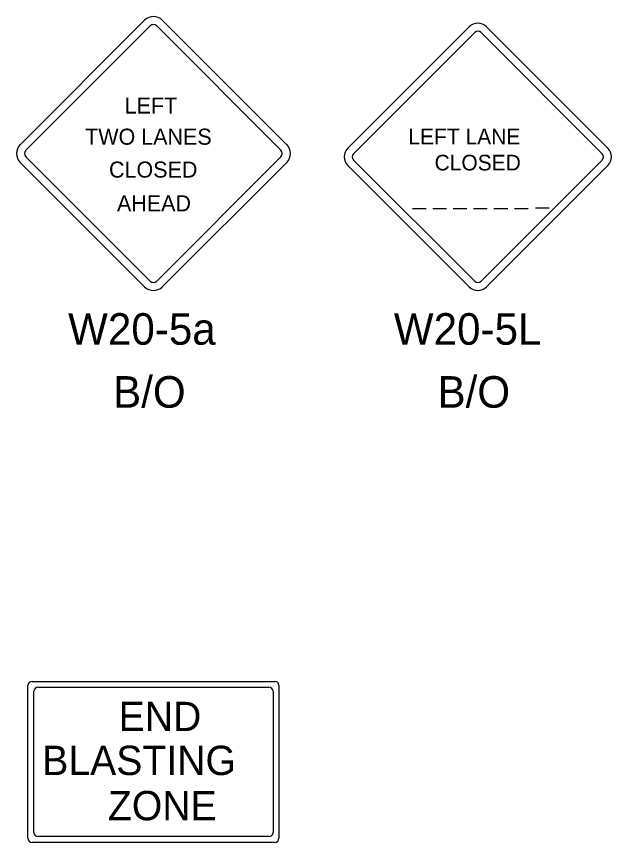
# Model space of a CAD drawing. Extents: x 10034 to 10794, y 10044 to 10499.
# Drawn here: x 10107.2 to 10173.2, y 10158.4 to 10250 of the extents above; entities that cross this region are included whole.
import ezdxf

# ---------------------------------------------------------------- set-up
doc = ezdxf.new("R2010")
doc.units = 0
for name, color, linetype in [('DSDate', 7, 'Continuous'), ('DSText', 7, 'Continuous'), ('DSTitle', 7, 'Continuous'), ('PlotBorder_dp', 7, 'Continuous')]:
    doc.layers.add(name, color=color, linetype=linetype)

msp = doc.modelspace()

# ---------------------------------------------------------------- linework, layer by layer
at = {"layer": 'DSDate'}
for p, q in [((10109.102, 10172.214), (10109.102, 10175.172)), ((10109.566, 10175.636), (10135.2, 10175.636)), ((10135.664, 10175.172), (10135.664, 10172.056)), ((10109.102, 10159.514), (10109.102, 10172.267)), ((10135.664, 10172.267), (10135.664, 10159.514)), ((10135.2, 10159.05), (10109.566, 10159.05))]:
    msp.add_line(p, q, dxfattribs=at)
for centre, start, end in [((10109.565, 10175.172), 90, 180), ((10135.199, 10175.172), 0, 90), ((10109.565, 10159.514), 180, 270), ((10135.199, 10159.514), 270, 0)]:
    msp.add_arc(centre, 0.464, start, end, dxfattribs=at)
at = {"layer": 'DSText'}
for p, q in [((10107.591, 10235.808), (10121.403, 10249.62)), ((10123.366, 10249.62), (10137.177, 10235.808)), ((10143.956, 10235.415), (10157.432, 10248.89)), ((10159.347, 10248.89), (10172.821, 10235.415)), ((10121.403, 10220.035), (10107.591, 10233.846)), ((10137.177, 10233.846), (10123.366, 10220.035)), ((10157.432, 10220.025), (10143.956, 10233.5)), ((10172.821, 10233.5), (10159.347, 10220.025)), ((10151.114, 10228.74), (10152.64, 10228.74)), ((10153.378, 10228.74), (10154.905, 10228.74)), ((10155.643, 10228.74), (10157.169, 10228.74)), ((10157.907, 10228.74), (10159.434, 10228.74)), ((10160.172, 10228.74), (10161.698, 10228.74)), ((10162.437, 10228.74), (10163.963, 10228.74)), ((10164.787, 10228.791), (10166.314, 10228.791)), ((10108.455, 10172.179), (10108.455, 10175.813)), ((10108.92, 10176.277), (10135.846, 10176.277)), ((10136.31, 10175.813), (10136.31, 10172.144)), ((10108.455, 10158.868), (10108.455, 10172.267)), ((10136.31, 10172.267), (10136.31, 10158.868)), ((10135.846, 10158.403), (10108.92, 10158.403))]:
    msp.add_line(p, q, dxfattribs=at)
for centre, radius, start, end in [((10122.383, 10248.635), 1.392, 45, 135), ((10158.387, 10247.928), 1.358, 45, 135), ((10108.576, 10234.829), 1.392, 135, 225), ((10136.189, 10234.829), 1.392, 315, 45), ((10144.918, 10234.458), 1.358, 135, 225), ((10171.857, 10234.458), 1.358, 315, 45), ((10122.386, 10221.02), 1.392, 225, 315), ((10158.391, 10220.987), 1.358, 225, 315), ((10108.919, 10175.813), 0.464, 90, 180), ((10135.846, 10175.813), 0.464, 0, 90), ((10108.919, 10158.867), 0.464, 180, 270), ((10135.846, 10158.867), 0.464, 270, 360)]:
    msp.add_arc(centre, radius, start, end, dxfattribs=at)
at = {"layer": 'DSTitle'}
for p, q in [((10108.233, 10235.184), (10122.028, 10248.978)), ((10122.741, 10248.978), (10136.535, 10235.184)), ((10144.582, 10234.806), (10158.041, 10248.263)), ((10158.737, 10248.263), (10172.195, 10234.806)), ((10122.028, 10220.676), (10108.233, 10234.471)), ((10136.535, 10234.471), (10122.741, 10220.676)), ((10158.041, 10220.652), (10144.582, 10234.109)), ((10172.195, 10234.109), (10158.737, 10220.652))]:
    msp.add_line(p, q, dxfattribs=at)
for centre, radius, start, end in [((10122.383, 10248.626), 0.502, 45, 135), ((10158.387, 10247.919), 0.49, 45, 135), ((10108.585, 10234.829), 0.502, 135, 225), ((10136.18, 10234.829), 0.502, 315, 45), ((10144.926, 10234.458), 0.49, 135, 225), ((10171.848, 10234.458), 0.49, 315, 45), ((10122.383, 10221.032), 0.502, 225, 315), ((10158.387, 10220.998), 0.49, 225, 315)]:
    msp.add_arc(centre, radius, start, end, dxfattribs=at)

# ---------------------------------------------------------------- texts
at = {"layer": 'PlotBorder_dp'}
for s, height, p in [('LEFT', 1.7823, (10119.191, 10239.261)), ('TWO LANES', 1.7834, (10114.802, 10235.806)), ('LEFT LANE', 1.7404, (10150.68, 10235.84)), ('CLOSED', 1.7404, (10153.583, 10232.951)), ('CLOSED', 1.7834, (10117.451, 10232.156)), ('AHEAD', 1.7823, (10118.335, 10228.413)), ('W20-5a', 3.5, (10112.908, 10213.62)), ('W20-5L', 3.5, (10149.056, 10213.62)), ('B/O', 3.5, (10117.898, 10206.634)), ('B/O', 3.5, (10153.902, 10206.634)), ('END', 3.2498, (10118.518, 10170.763)), ('BLASTING', 3.2498, (10110.042, 10165.887)), ('ZONE', 3.2498, (10117.328, 10160.87))]:
    msp.add_text(s, height=height, dxfattribs=at).set_placement(p)

doc.saveas('drawing.dxf')
